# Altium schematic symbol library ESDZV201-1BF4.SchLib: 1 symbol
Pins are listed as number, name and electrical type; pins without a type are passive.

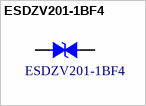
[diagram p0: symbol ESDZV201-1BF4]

## ESDZV201-1BF4
designator D?
footprint ST_0201B_CSP_ap
pins: 1, 2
